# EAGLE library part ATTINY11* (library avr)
MICROCONTROLLER 1 Kbytes FLASH
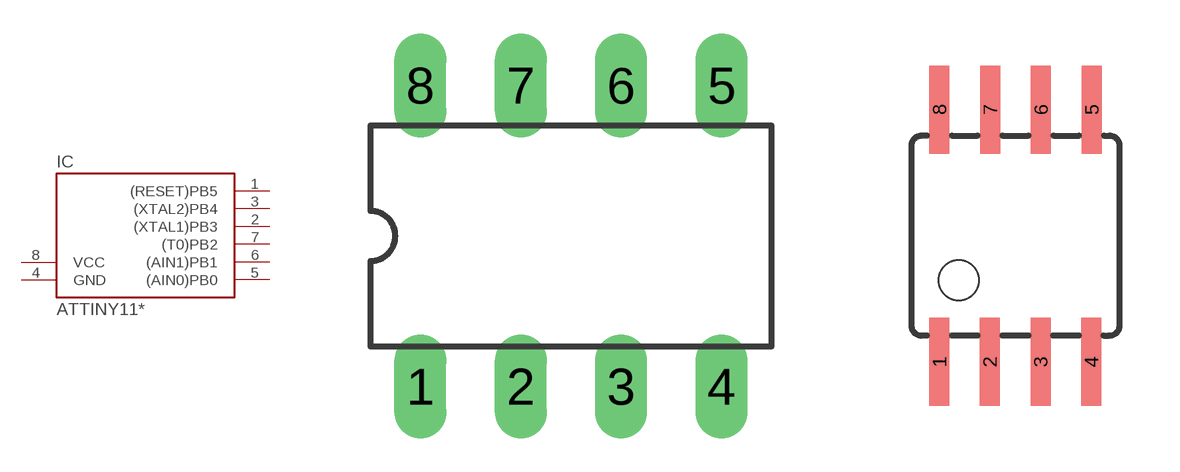
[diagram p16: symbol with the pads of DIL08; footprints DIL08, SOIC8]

Designator prefix IC

## ATTINY11-6P, ATTINY11L-2P  [DIL08]
1  (RESET)PB5
2  (XTAL1)PB3
3  (XTAL2)PB4
4  GND  pwr
5  (AIN0)PB0
6  (AIN1)PB1
7  (T0)PB2
8  VCC  pwr

## ATTINY11-6S, ATTINY11L-2S  [SOIC8]
Pads as for DIL08

## Footprint DIL08 (pad centres in mm)
Dual In Line
drill 0.813 long: 1 -3.81,-3.81; 2 -1.27,-3.81; 3 1.27,-3.81; 4 3.81,-3.81; 5 3.81,3.81; 6 1.27,3.81; 7 -1.27,3.81; 8 -3.81,3.81

## Footprint SOIC8 (pad centres in mm)
Wide Plastic Gull Wing Small Outline Package
smd 0.5 x 2.2: 1 -1.905,-3.154; 2 -0.645,-3.154; 3 0.625,-3.154; 4 1.895,-3.154; 5 1.905,3.154; 6 0.635,3.154; 7 -0.635,3.154; 8 -1.905,3.154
